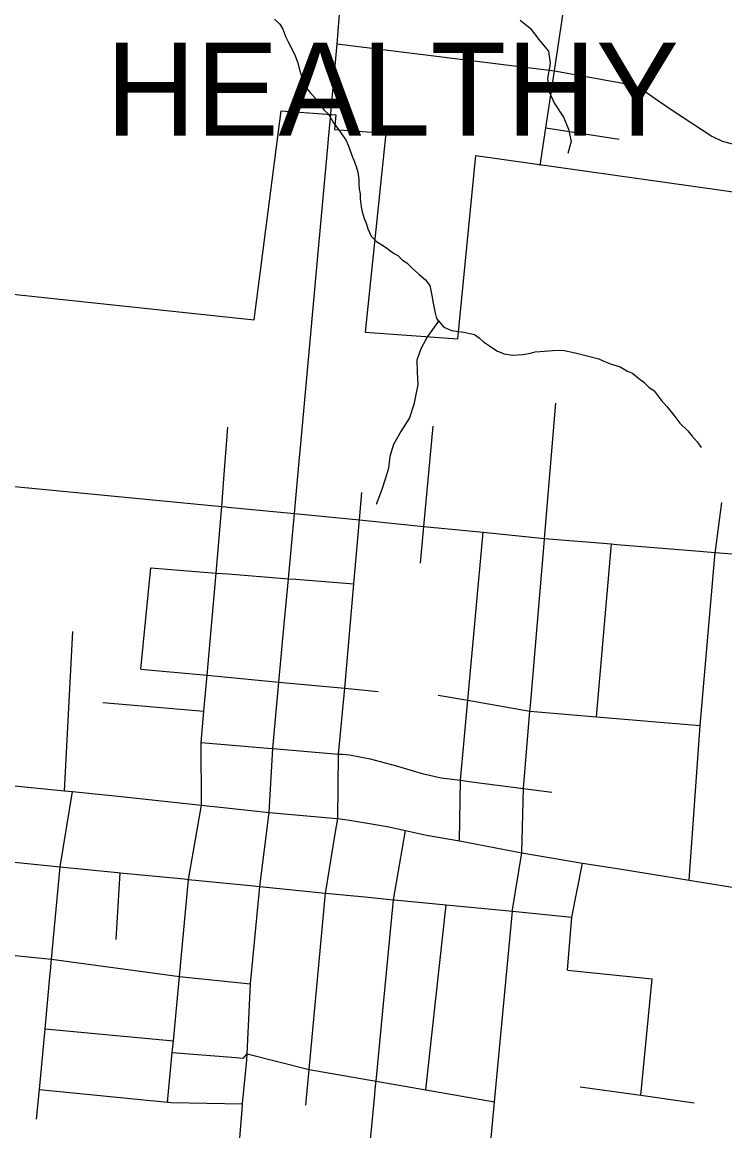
# Model space of a CAD drawing. Extents: x 0 to 34, y 0 to 22.
# Drawn here: x 6.256 to 6.973, y 15.927 to 17.057 of the extents above; entities that cross this region are included whole.
import ezdxf

# ---------------------------------------------------------------- set-up
doc = ezdxf.new("R2010")
doc.units = 0
for name, color, linetype in [('GM_X_City_Street', 7, 'Continuous'), ('GM_X_Corporation', 7, 'Continuous'), ('GM_X_Corporation_Text', 7, 'Continuous'), ('GM_X_County_Road', 7, 'Continuous'), ('GM_X_Minor_River', 7, 'Continuous'), ('GM_X_Township_Subdivision', 7, 'Continuous'), ('GM_X_US_Route', 7, 'Continuous')]:
    doc.layers.add(name, color=color, linetype=linetype)

msp = doc.modelspace()

# ---------------------------------------------------------------- linework, layer by layer
at = {"layer": 'GM_X_City_Street'}
for points in [[(6.7887, 16.5295), (6.7888, 16.5307), (6.8004, 16.6687)], [(6.4045, 15.9559), (6.4093, 16.0066), (6.4104, 16.0183), (6.4166, 16.084), (6.4259, 16.183), (6.439, 16.2586), (6.4387, 16.3225), (6.4416, 16.3547), (6.4449, 16.3912), (6.4542, 16.4954), (6.4597, 16.5634), (6.462, 16.5914), (6.4658, 16.6441)], [(6.6623, 16.5056), (6.6658, 16.543), (6.6752, 16.6452)], [(6.0405, 16.6037), (6.4597, 16.5634), (6.4644, 16.563), (6.4661, 16.5628)], [(6.5999, 16.5461), (6.6, 16.5474), (6.6002, 16.5496), (6.6027, 16.5776)], [(6.4661, 16.5628), (6.5338, 16.5563), (6.6002, 16.5496), (6.6658, 16.543), (6.7262, 16.537), (6.7888, 16.5307), (6.857, 16.5251), (6.8624, 16.5247), (6.9426, 16.5182)], [(6.963, 16.5182), (6.9696, 16.5673)], [(6.5754, 16.2294), (6.578, 16.245), (6.5788, 16.3109), (6.5851, 16.3779), (6.5945, 16.4844), (6.5999, 16.5461)], [(6.7022, 16.2224), (6.7032, 16.2841), (6.7106, 16.3658), (6.7262, 16.537)], [(6.7744, 16.3605), (6.7887, 16.5295), (6.7887, 16.5295)], [(6.8418, 16.349), (6.857, 16.5251)], [(6.9364, 16.1823), (6.9475, 16.34), (6.9628, 16.5165), (6.963, 16.5175), (6.963, 16.5182)], [(6.9426, 16.5182), (6.9628, 16.5165), (7.0315, 16.511), (7.0972, 16.503), (7.1529, 16.4963)], [(6.3772, 16.3975), (6.3874, 16.5007)], [(6.3874, 16.5007), (6.4542, 16.4954), (6.4663, 16.4945), (6.4663, 16.4945)], [(6.4663, 16.4945), (6.5277, 16.4897), (6.5353, 16.4891)], [(6.5353, 16.4891), (6.5353, 16.4891), (6.5945, 16.4844)], [(6.2994, 16.2734), (6.3081, 16.4359)], [(6.3772, 16.3975), (6.4449, 16.3912), (6.518, 16.3843), (6.5851, 16.3779), (6.6192, 16.3747)], [(6.6803, 16.3711), (6.7106, 16.3658), (6.7739, 16.3547), (6.8418, 16.349), (6.9475, 16.34)], [(6.3384, 16.3634), (6.4416, 16.3547)], [(6.7563, 16.1521), (6.7657, 16.2103), (6.7672, 16.2758), (6.7739, 16.3547), (6.7744, 16.3605), (6.7744, 16.3605)], [(6.4387, 16.3225), (6.5108, 16.3165), (6.5109, 16.3165)], [(6.5109, 16.3165), (6.5117, 16.3165), (6.5788, 16.3109), (6.5828, 16.3106), (6.5831, 16.3106)], [(5.9866, 16.3066), (6.0139, 16.3035), (6.1281, 16.2913), (6.2279, 16.2806), (6.2994, 16.2734), (6.3075, 16.2727), (6.3572, 16.2675), (6.439, 16.2586), (6.4481, 16.2577)], [(6.5831, 16.3106), (6.59, 16.31), (6.6112, 16.3061), (6.6365, 16.2991), (6.6641, 16.2909), (6.6834, 16.2867), (6.7032, 16.2841), (6.7142, 16.2827), (6.7143, 16.2827)], [(6.7143, 16.2827), (6.7672, 16.2758), (6.7964, 16.272)], [(6.285, 16.0898), (6.2862, 16.1018), (6.2949, 16.1959), (6.3075, 16.2727)], [(6.4481, 16.2577), (6.452, 16.2573), (6.5082, 16.2512), (6.5734, 16.2454)], [(6.5734, 16.2454), (6.578, 16.245), (6.5901, 16.2435), (6.6146, 16.2395), (6.6283, 16.2369), (6.647, 16.2328), (6.6684, 16.2283), (6.7022, 16.2224), (6.7657, 16.2103), (6.8275, 16.1996), (6.8652, 16.1938), (6.9364, 16.1823), (7.0493, 16.1641), (7.0869, 16.158), (7.13, 16.1509), (7.1731, 16.1436), (7.1741, 16.1434)], [(6.5454, 15.953), (6.5488, 15.9891), (6.5656, 16.1692), (6.5657, 16.1707), (6.5754, 16.2294)], [(6.6157, 15.9635), (6.6163, 15.9695), (6.617, 15.9772), (6.6239, 16.0489), (6.635, 16.1624), (6.647, 16.2328)], [(6.213, 16.2039), (6.2382, 16.2015), (6.2949, 16.1959), (6.3501, 16.1905)], [(6.3501, 16.1905), (6.3537, 16.1901), (6.3563, 16.1899), (6.4213, 16.1835)], [(6.3522, 16.1218), (6.3563, 16.1899)], [(6.8122, 16.0904), (6.8167, 16.1447), (6.8275, 16.1996)], [(6.4213, 16.1835), (6.4241, 16.1832), (6.4259, 16.183), (6.4925, 16.1765)], [(6.4925, 16.1765), (6.4945, 16.1763), (6.4985, 16.1759), (6.5656, 16.1692), (6.6055, 16.1653), (6.635, 16.1624)], [(6.635, 16.1624), (6.6357, 16.1623), (6.6887, 16.1571), (6.7561, 16.1506), (6.8167, 16.1447)], [(6.6677, 15.9684), (6.6887, 16.1571)], [(6.7292, 15.8641), (6.7295, 15.8678), (6.7378, 15.9562), (6.7561, 16.1506), (6.7562, 16.1518), (6.7563, 16.1521)], [(6.2352, 16.1067), (6.2354, 16.1067), (6.2862, 16.1018), (6.4166, 16.084), (6.4891, 16.0765)], [(6.271, 15.9385), (6.2738, 15.9689), (6.2796, 16.0307), (6.2848, 16.0875), (6.285, 16.0898)], [(6.8122, 16.0904), (6.8986, 16.0817)], [(6.8871, 15.9629), (6.8986, 16.0817)], [(6.2796, 16.0307), (6.4104, 16.0183)], [(6.4093, 16.0066), (6.4699, 16.0017), (6.4701, 16.0017)], [(6.4701, 16.0017), (6.482, 16.0008), (6.4857, 16.0051), (6.5488, 15.9891), (6.617, 15.9772), (6.6677, 15.9684), (6.7378, 15.9562)], [(6.2738, 15.9689), (6.4045, 15.9559), (6.4061, 15.9558), (6.4082, 15.9557)], [(6.6042, 15.8442), (6.6083, 15.8863), (6.6157, 15.9635)], [(6.8252, 15.9715), (6.8871, 15.9629), (6.9415, 15.9553)], [(6.4082, 15.9557), (6.4809, 15.9541)]]:
    msp.add_lwpolyline(points, dxfattribs=at)
at = {"layer": 'GM_X_Corporation'}
msp.add_lwpolyline([(6.1981, 17.0859), (6.1729, 16.7878), (6.4927, 16.7536), (6.5203, 16.9669), (6.5761, 16.9627), (6.5748, 16.9477), (6.6269, 16.944), (6.6059, 16.7411), (6.7005, 16.7344), (6.7188, 16.9212), (7.1642, 16.8585)], dxfattribs=at)
at = {"layer": 'GM_X_County_Road'}
msp.add_lwpolyline([(6.5773, 17.0352), (6.799, 17.0076), (6.8744, 16.994), (6.8855, 16.9906), (6.9051, 16.9769), (6.9189, 16.9674), (6.9593, 16.9408), (6.9699, 16.9359), (7.0092, 16.9255)], dxfattribs=at)
at = {"layer": 'GM_X_Minor_River'}
for points in [[(6.5135, 17.0602), (6.519, 17.0551), (6.5219, 17.0501), (6.5251, 17.042), (6.5277, 17.0366), (6.532, 17.0285), (6.5345, 17.0227), (6.5374, 17.0157), (6.5387, 17.01), (6.5408, 17.0031), (6.5448, 16.9946), (6.5465, 16.9896), (6.5506, 16.9845), (6.558, 16.9767), (6.5638, 16.9678), (6.5686, 16.9635), (6.5737, 16.9545), (6.5781, 16.9487), (6.5818, 16.9433), (6.5862, 16.9371), (6.5887, 16.9317), (6.5926, 16.9205), (6.5951, 16.9147), (6.5969, 16.9101), (6.5986, 16.9044), (6.5996, 16.8971), (6.5994, 16.8925), (6.6, 16.8868), (6.6007, 16.8822), (6.6009, 16.8772), (6.6018, 16.8688), (6.6028, 16.8639), (6.6049, 16.857), (6.6071, 16.8523), (6.6088, 16.8466), (6.612, 16.8389), (6.6176, 16.8334), (6.6266, 16.8278), (6.6348, 16.8215), (6.6393, 16.8194), (6.6441, 16.8144), (6.6486, 16.8119), (6.6538, 16.8065), (6.6608, 16.8002), (6.6675, 16.7943), (6.6719, 16.7888), (6.6739, 16.7785), (6.6752, 16.7708), (6.6762, 16.7655), (6.6772, 16.7605), (6.6786, 16.7551), (6.6863, 16.7461), (6.6939, 16.7429), (6.6988, 16.742), (6.7067, 16.741), (6.7128, 16.7397), (6.7173, 16.7388), (6.7222, 16.7352), (6.7266, 16.7313), (6.7326, 16.727), (6.7401, 16.7222), (6.7476, 16.7189), (6.7563, 16.7175), (6.7666, 16.7184), (6.7746, 16.7197), (6.7792, 16.7211), (6.7845, 16.7213), (6.7971, 16.7225), (6.8074, 16.7226), (6.8199, 16.7199), (6.8335, 16.7165), (6.8441, 16.7139), (6.8493, 16.7115), (6.8561, 16.7087), (6.8659, 16.7057), (6.8734, 16.7013), (6.8786, 16.6993), (6.885, 16.6938), (6.8902, 16.6902), (6.895, 16.6851), (6.9006, 16.6811), (6.9076, 16.6718), (6.9135, 16.6652), (6.9205, 16.6566), (6.9267, 16.6484), (6.9348, 16.6406), (6.9393, 16.6351), (6.9444, 16.6293), (6.9485, 16.6236)], [(6.7639, 17.0593), (6.7743, 17.0511), (6.7839, 17.038), (6.7928, 17.0276), (6.7944, 17.015), (6.7918, 16.9999), (6.7934, 16.9861), (6.7989, 16.9743), (6.8081, 16.9604), (6.8131, 16.9481), (6.8159, 16.9355), (6.8126, 16.9231)], [(6.6812, 16.7521), (6.6796, 16.7511), (6.6694, 16.7365), (6.6626, 16.7241), (6.6585, 16.7125), (6.659, 16.7003), (6.6598, 16.6873), (6.6577, 16.6775), (6.6555, 16.6673), (6.651, 16.6537), (6.6423, 16.6398), (6.6348, 16.6267), (6.6311, 16.6142), (6.6297, 16.6025), (6.6267, 16.5923), (6.6226, 16.5795), (6.617, 16.5655)]]:
    msp.add_lwpolyline(points, dxfattribs=at)
at = {"layer": 'GM_X_Township_Subdivision'}
for points in [[(6.7844, 16.9112), (6.7902, 16.9495), (6.799, 17.0076), (6.8079, 17.0668), (6.8133, 17.1023), (6.8178, 17.1319), (6.8167, 17.1402), (6.8123, 17.154), (6.8001, 17.1868), (6.7932, 17.2092), (6.7932, 17.218), (6.7964, 17.2316), (6.7931, 17.275)], [(6.7902, 16.9495), (6.8648, 16.938)]]:
    msp.add_lwpolyline(points, dxfattribs=at)
at = {"layer": 'GM_X_US_Route'}
for points in [[(6.5713, 16.9682), (6.5773, 17.0352), (6.5796, 17.0608), (6.5848, 17.1183), (6.5857, 17.1275)], [(6.5686, 16.9383), (6.5705, 16.9598), (6.5713, 16.9682)], [(6.5396, 16.6197), (6.5499, 16.732), (6.5568, 16.8072), (6.5679, 16.93), (6.5686, 16.9383)], [(6.4852, 15.999), (6.4857, 16.0051), (6.4891, 16.0765), (6.4985, 16.1759), (6.5082, 16.2512), (6.5117, 16.3165), (6.518, 16.3843), (6.5238, 16.4471), (6.5277, 16.4897), (6.5338, 16.5563), (6.5391, 16.6133), (6.5396, 16.6197)], [(6.4804, 15.9485), (6.4809, 15.9541), (6.4841, 15.985), (6.4852, 15.999)], [(6.4766, 15.898), (6.4779, 15.9151), (6.4804, 15.9485)]]:
    msp.add_lwpolyline(points, dxfattribs=at)

# ---------------------------------------------------------------- texts
at = {"layer": 'GM_X_Corporation_Text'}
msp.add_text('HEALTHY', height=0.0947, rotation=0, dxfattribs=at).set_placement((6.3417, 16.9415))

doc.saveas('drawing.dxf')
